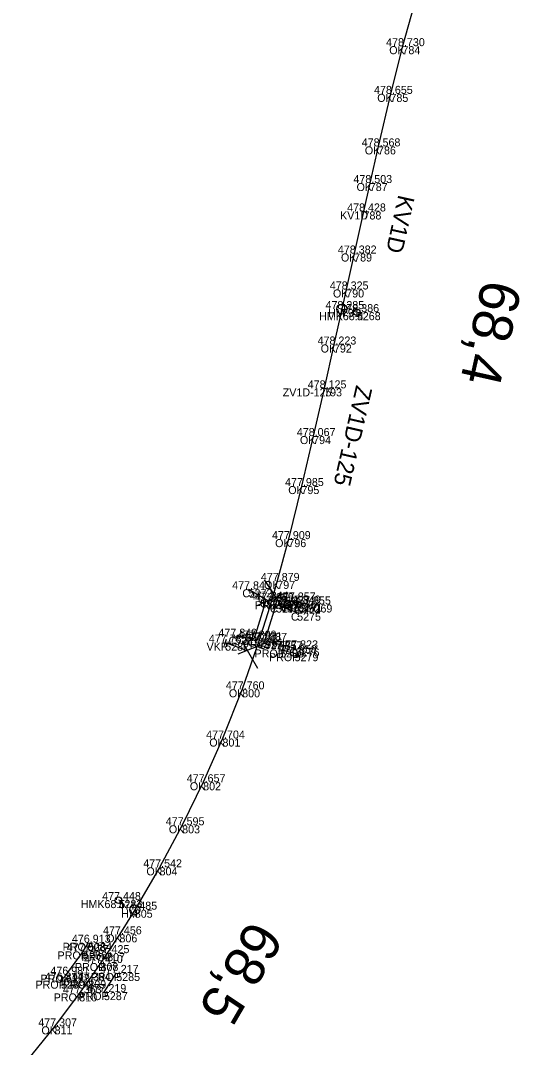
# Model space of a CAD drawing. Extents: x -621782 to -610392, y -1141853 to -1122321.
# Drawn here: x -621544.5 to -621469.5, y -1125343.5 to -1125189.6 of the extents above; entities that cross this region are included whole.
import ezdxf

# ---------------------------------------------------------------- set-up
doc = ezdxf.new("R2010")
doc.units = 0
for name, color, linetype in [('Vrstva 1', 7, 'Continuous'), ('Vrstva 19', 7, 'Continuous'), ('Vrstva 2', 7, 'Continuous'), ('Vrstva 4', 7, 'Continuous'), ('Vrstva 51', 7, 'Continuous'), ('Vrstva 60', 7, 'Continuous'), ('Vrstva 61', 7, 'Continuous'), ('Vrstva 62', 7, 'Continuous'), ('Vrstva 7', 7, 'Continuous')]:
    doc.layers.add(name, color=color, linetype=linetype)

msp = doc.modelspace()

# ---------------------------------------------------------------- linework, layer by layer
at = {"layer": 'Vrstva 1'}
msp.add_lwpolyline([(-621485.04, -1125185.72), (-621487.19, -1125193.41), (-621488.99, -1125200.56), (-621490.85, -1125208.43), (-621492.09, -1125213.92), (-621493.03, -1125218.18), (-621494.43, -1125224.48), (-621495.62, -1125229.87), (-621496.28, -1125232.81), (-621497.46, -1125238.12), (-621498.93, -1125244.69), (-621500.58, -1125251.84), (-621502.33, -1125259.33), (-621504.29, -1125267.28), (-621505.96, -1125273.55), (-621506.84, -1125276.59), (-621508.65, -1125282.44), (-621511.22, -1125289.79), (-621514.17, -1125297.17), (-621517.07, -1125303.72), (-621520.22, -1125310.17), (-621523.6, -1125316.47), (-621527.32, -1125322.82), (-621529.62, -1125326.51), (-621531.47, -1125329.33), (-621532.46, -1125330.81), (-621534.28, -1125333.44), (-621535.65, -1125335.36), (-621539.34, -1125340.3), (-621544.45, -1125346.63)], dxfattribs=at)
at = {"layer": 'Vrstva 19'}
for p, q in [((-621503.56, -1125276.48), (-621501.27, -1125277.08)), ((-621505.53, -1125283.82), (-621503.36, -1125284.38)), ((-621530.1, -1125332.29), (-621531.95, -1125335.17))]:
    msp.add_line(p, q, dxfattribs=at)
msp.add_lwpolyline([(-621538.38, -1125333.45), (-621537.62, -1125332.56), (-621535.07, -1125329.07), (-621534.3, -1125327.77)], dxfattribs=at)
at = {"layer": 'Vrstva 2'}
for p, q in [((-621492.54, -1125218.29), (-621493.52, -1125218.07)), ((-621498.45, -1125244.8), (-621499.42, -1125244.58))]:
    msp.add_line(p, q, dxfattribs=at)
at = {"layer": 'Vrstva 4'}
for p, q in [((-621505.32, -1125277.25), (-621507.86, -1125273.4)), ((-621508.96, -1125277.25), (-621504.77, -1125275.33)), ((-621502.79, -1125276.94), (-621506.17, -1125275.97)), ((-621506.84, -1125276.59), (-621508.65, -1125282.44)), ((-621502.92, -1125277.42), (-621502.65, -1125276.46)), ((-621513.6, -1125282.32), (-621513.93, -1125283.27)), ((-621513.77, -1125282.79), (-621510.45, -1125283.96)), ((-621507.59, -1125282.84), (-621511.88, -1125284.52)), ((-621511.22, -1125282.63), (-621508.91, -1125286.62))]:
    msp.add_line(p, q, dxfattribs=at)
at = {"layer": 'Vrstva 51'}
for points in [[(-621510.26, -1125274.8), (-621507.62, -1125276.35), (-621509.42, -1125282.19), (-621512.32, -1125281.91)], [(-621503.2, -1125283.66), (-621507.84, -1125282.53), (-621506.14, -1125277.09), (-621502.98, -1125278.3)]]:
    msp.add_lwpolyline(points, dxfattribs=at)
at = {"layer": 'Vrstva 60'}
for p, q in [((-621487.19, -1125193.41), (-621487.19, -1125193.41)), ((-621488.99, -1125200.56), (-621488.99, -1125200.56)), ((-621490.85, -1125208.43), (-621490.85, -1125208.43)), ((-621492.09, -1125213.92), (-621492.09, -1125213.92)), ((-621493.03, -1125218.18), (-621493.03, -1125218.18)), ((-621494.43, -1125224.48), (-621494.43, -1125224.48)), ((-621495.62, -1125229.87), (-621495.62, -1125229.87)), ((-621496.28, -1125232.81), (-621496.28, -1125232.81)), ((-621494.03, -1125233.27), (-621494.03, -1125233.27)), ((-621497.46, -1125238.12), (-621497.46, -1125238.12)), ((-621498.93, -1125244.69), (-621498.93, -1125244.69)), ((-621500.58, -1125251.84), (-621500.58, -1125251.84)), ((-621502.33, -1125259.33), (-621502.33, -1125259.33)), ((-621504.29, -1125267.28), (-621504.29, -1125267.28)), ((-621510.26, -1125274.8), (-621510.26, -1125274.8)), ((-621505.96, -1125273.55), (-621505.96, -1125273.55)), ((-621507.62, -1125276.35), (-621507.62, -1125276.35)), ((-621506.84, -1125276.59), (-621506.84, -1125276.59)), ((-621506.14, -1125277.09), (-621506.14, -1125277.09)), ((-621503.56, -1125276.48), (-621503.56, -1125276.48)), ((-621502.79, -1125276.94), (-621502.79, -1125276.94)), ((-621501.27, -1125277.08), (-621501.27, -1125277.08)), ((-621502.98, -1125278.3), (-621502.98, -1125278.3)), ((-621512.32, -1125281.91), (-621512.32, -1125281.91)), ((-621509.42, -1125282.19), (-621509.42, -1125282.19)), ((-621508.65, -1125282.44), (-621508.65, -1125282.44)), ((-621507.84, -1125282.53), (-621507.84, -1125282.53)), ((-621513.77, -1125282.79), (-621513.77, -1125282.79)), ((-621505.53, -1125283.82), (-621505.53, -1125283.82)), ((-621503.2, -1125283.66), (-621503.2, -1125283.66)), ((-621503.36, -1125284.38), (-621503.36, -1125284.38)), ((-621511.22, -1125289.79), (-621511.22, -1125289.79)), ((-621514.17, -1125297.17), (-621514.17, -1125297.17)), ((-621517.07, -1125303.72), (-621517.07, -1125303.72)), ((-621520.22, -1125310.17), (-621520.22, -1125310.17)), ((-621523.6, -1125316.47), (-621523.6, -1125316.47)), ((-621529.76, -1125321.38), (-621529.76, -1125321.38)), ((-621527.32, -1125322.82), (-621527.32, -1125322.82)), ((-621529.62, -1125326.51), (-621529.62, -1125326.51)), ((-621534.3, -1125327.77), (-621534.3, -1125327.77)), ((-621535.07, -1125329.07), (-621535.07, -1125329.07)), ((-621531.47, -1125329.33), (-621531.47, -1125329.33)), ((-621532.46, -1125330.81), (-621532.46, -1125330.81)), ((-621537.62, -1125332.56), (-621537.62, -1125332.56)), ((-621530.1, -1125332.29), (-621530.1, -1125332.29)), ((-621538.38, -1125333.45), (-621538.38, -1125333.45)), ((-621534.28, -1125333.44), (-621534.28, -1125333.44)), ((-621535.65, -1125335.36), (-621535.65, -1125335.36)), ((-621531.95, -1125335.17), (-621531.95, -1125335.17)), ((-621539.34, -1125340.3), (-621539.34, -1125340.3))]:
    msp.add_line(p, q, dxfattribs=at)
at = {"layer": 'Vrstva 7'}
for p, q in [((-621494.02, -1125233.22), (-621494.04, -1125233.32)), ((-621529.73, -1125321.34), (-621529.78, -1125321.43))]:
    msp.add_line(p, q, dxfattribs=at)
for centre, radius in [((-621496.28, -1125232.81), 0.75), ((-621494.03, -1125233.27), 0.5), ((-621529.76, -1125321.38), 0.5), ((-621527.32, -1125322.82), 0.75)]:
    msp.add_circle(centre, radius, dxfattribs=at)

# ---------------------------------------------------------------- texts
at = {"layer": 'Vrstva 2'}
for s, rotation, p in [('KV1D', 257.5049, (-621487.79, -1125215.58)), ('ZV1D-125', 257.0698, (-621494.12, -1125244.13))]:
    msp.add_text(s, height=2.5, rotation=rotation, dxfattribs=at).set_placement(p)
at = {"layer": 'Vrstva 60'}
for s, p in [('784', (-621487.19, -1125194.61)), ('785', (-621488.99, -1125201.76)), ('786', (-621490.85, -1125209.63)), ('787', (-621492.09, -1125215.12)), ('788', (-621493.03, -1125219.38)), ('789', (-621494.43, -1125225.68)), ('790', (-621495.62, -1125231.07)), ('791', (-621496.28, -1125234.01)), ('5268', (-621494.03, -1125234.47)), ('792', (-621497.46, -1125239.32)), ('793', (-621498.93, -1125245.89)), ('794', (-621500.58, -1125253.04)), ('795', (-621502.33, -1125260.53)), ('796', (-621504.29, -1125268.48)), ('5272', (-621510.26, -1125276)), ('797', (-621505.96, -1125274.75)), ('5273', (-621507.62, -1125277.55)), ('798', (-621506.84, -1125277.79)), ('5274', (-621506.14, -1125278.29)), ('5270', (-621503.56, -1125277.68)), ('5271', (-621502.79, -1125278.14)), ('5269', (-621501.27, -1125278.28)), ('5275', (-621502.98, -1125279.5)), ('5281', (-621512.32, -1125283.11)), ('5278', (-621509.42, -1125283.39)), ('799', (-621508.65, -1125283.64)), ('5277', (-621507.84, -1125283.73)), ('5282', (-621513.77, -1125284)), ('5280', (-621505.53, -1125285.02)), ('5276', (-621503.2, -1125284.85)), ('5279', (-621503.36, -1125285.58)), ('800', (-621511.22, -1125290.99)), ('801', (-621514.17, -1125298.37)), ('802', (-621517.07, -1125304.92)), ('803', (-621520.22, -1125311.37)), ('804', (-621523.6, -1125317.67)), ('5283', (-621529.76, -1125322.58)), ('805', (-621527.32, -1125324.02)), ('806', (-621529.62, -1125327.71)), ('5284', (-621534.3, -1125328.97)), ('5286', (-621535.07, -1125330.27)), ('807', (-621531.47, -1125330.53)), ('808', (-621532.46, -1125332.01)), ('5288', (-621537.62, -1125333.76)), ('5285', (-621530.1, -1125333.5)), ('5289', (-621538.38, -1125334.65)), ('809', (-621534.28, -1125334.64)), ('810', (-621535.65, -1125336.56)), ('5287', (-621531.95, -1125336.37)), ('811', (-621539.34, -1125341.5))]:
    msp.add_text(s, height=1.2, dxfattribs=at).set_placement(p)
at = {"layer": 'Vrstva 61'}
for s, p in [('478.730', (-621489.64, -1125193.41)), ('478.655', (-621491.45, -1125200.56)), ('478.568', (-621493.3, -1125208.43)), ('478.503', (-621494.54, -1125213.92)), ('478.428', (-621495.48, -1125218.18)), ('478.382', (-621496.87, -1125224.48)), ('478.325', (-621498.08, -1125229.87)), ('478.285', (-621498.73, -1125232.81)), ('478.386', (-621496.49, -1125233.27)), ('478.223', (-621499.91, -1125238.12)), ('478.125', (-621501.39, -1125244.69)), ('478.067', (-621503.03, -1125251.84)), ('477.985', (-621504.79, -1125259.33)), ('477.909', (-621506.75, -1125267.28)), ('477.879', (-621508.42, -1125273.55)), ('477.843', (-621512.72, -1125274.8)), ('477.844', (-621510.07, -1125276.35)), ('477.869', (-621509.29, -1125276.59)), ('477.913', (-621508.59, -1125277.09)), ('477.857', (-621506.01, -1125276.48)), ('477.849', (-621505.24, -1125276.94)), ('477.855', (-621503.72, -1125277.08)), ('477.870', (-621505.43, -1125278.3)), ('477.849', (-621514.78, -1125281.91)), ('477.809', (-621511.87, -1125282.19)), ('477.785', (-621516.22, -1125282.79)), ('477.831', (-621511, -1125282.44)), ('477.887', (-621510.29, -1125282.53)), ('477.823', (-621505.65, -1125283.66)), ('477.857', (-621507.98, -1125283.82)), ('477.858', (-621505.82, -1125284.38)), ('477.760', (-621513.67, -1125289.79)), ('477.704', (-621516.62, -1125297.17)), ('477.657', (-621519.53, -1125303.72)), ('477.595', (-621522.68, -1125310.17)), ('477.542', (-621526.05, -1125316.47)), ('477.448', (-621532.21, -1125321.38)), ('477.485', (-621529.77, -1125322.82)), ('477.456', (-621532.08, -1125326.51)), ('476.913', (-621536.75, -1125327.77)), ('477.003', (-621537.52, -1125329.07)), ('477.425', (-621533.93, -1125329.33)), ('477.410', (-621534.91, -1125330.81)), ('476.981', (-621539.97, -1125332.56)), ('477.217', (-621532.55, -1125332.29)), ('476.814', (-621540.83, -1125333.45)), ('477.384', (-621536.73, -1125333.44)), ('477.363', (-621538.1, -1125335.36)), ('477.219', (-621534.4, -1125335.17)), ('477.307', (-621541.79, -1125340.3))]:
    msp.add_text(s, height=1.2, dxfattribs=at).set_placement(p)
at = {"layer": 'Vrstva 62'}
for s, p in [('OK', (-621489.17, -1125194.61)), ('OK', (-621490.97, -1125201.76)), ('OK', (-621492.83, -1125209.63)), ('OK', (-621494.07, -1125215.12)), ('KV1D', (-621496.54, -1125219.38)), ('OK', (-621496.41, -1125225.68)), ('OK', (-621497.61, -1125231.07)), ('HMK68.4', (-621499.7, -1125234.47)), ('HM', (-621498.31, -1125234.01)), ('OK', (-621499.45, -1125239.32)), ('ZV1D-125', (-621505.14, -1125245.89)), ('OK', (-621502.56, -1125253.04)), ('OK', (-621504.31, -1125260.53)), ('OK', (-621506.28, -1125268.48)), ('C', (-621511.2, -1125276)), ('OK', (-621507.95, -1125274.75)), ('C', (-621508.55, -1125277.55)), ('PRJ', (-621509.32, -1125277.79)), ('PROP', (-621507.39, -1125277.68)), ('C', (-621507.07, -1125278.29)), ('VKR', (-621505.59, -1125278.14)), ('PROP', (-621505.1, -1125278.28)), ('C', (-621503.91, -1125279.5)), ('C', (-621513.26, -1125283.11)), ('PRJ', (-621511.13, -1125283.64)), ('C', (-621510.36, -1125283.39)), ('C', (-621508.77, -1125283.73)), ('VKR', (-621516.57, -1125284)), ('PROP', (-621509.36, -1125285.02)), ('C', (-621504.14, -1125284.85)), ('PROP', (-621507.2, -1125285.58)), ('OK', (-621513.21, -1125290.99)), ('OK', (-621516.15, -1125298.37)), ('OK', (-621519.06, -1125304.92)), ('OK', (-621522.21, -1125311.37)), ('OK', (-621525.58, -1125317.67)), ('HMK68.5', (-621535.43, -1125322.58)), ('HM', (-621529.35, -1125324.02)), ('OK', (-621531.61, -1125327.71)), ('PROP', (-621538.14, -1125328.97)), ('PROP', (-621538.9, -1125330.27)), ('PROP', (-621535.31, -1125330.53)), ('PROP', (-621536.3, -1125332.01)), ('PROP', (-621541.45, -1125333.76)), ('PROP', (-621533.93, -1125333.5)), ('PROP', (-621542.21, -1125334.65)), ('PROP', (-621538.12, -1125334.64)), ('PROP', (-621539.48, -1125336.56)), ('PROP', (-621535.78, -1125336.37)), ('OK', (-621541.32, -1125341.5))]:
    msp.add_text(s, height=1.2, dxfattribs=at).set_placement(p)
at = {"layer": 'Vrstva 7'}
for s, rotation, p in [('68,4', 257.3752, (-621475.12, -1125228.18)), ('68,5', 239.6568, (-621510.01, -1125324.1))]:
    msp.add_text(s, height=6, rotation=rotation, dxfattribs=at).set_placement(p)

doc.saveas('drawing.dxf')
